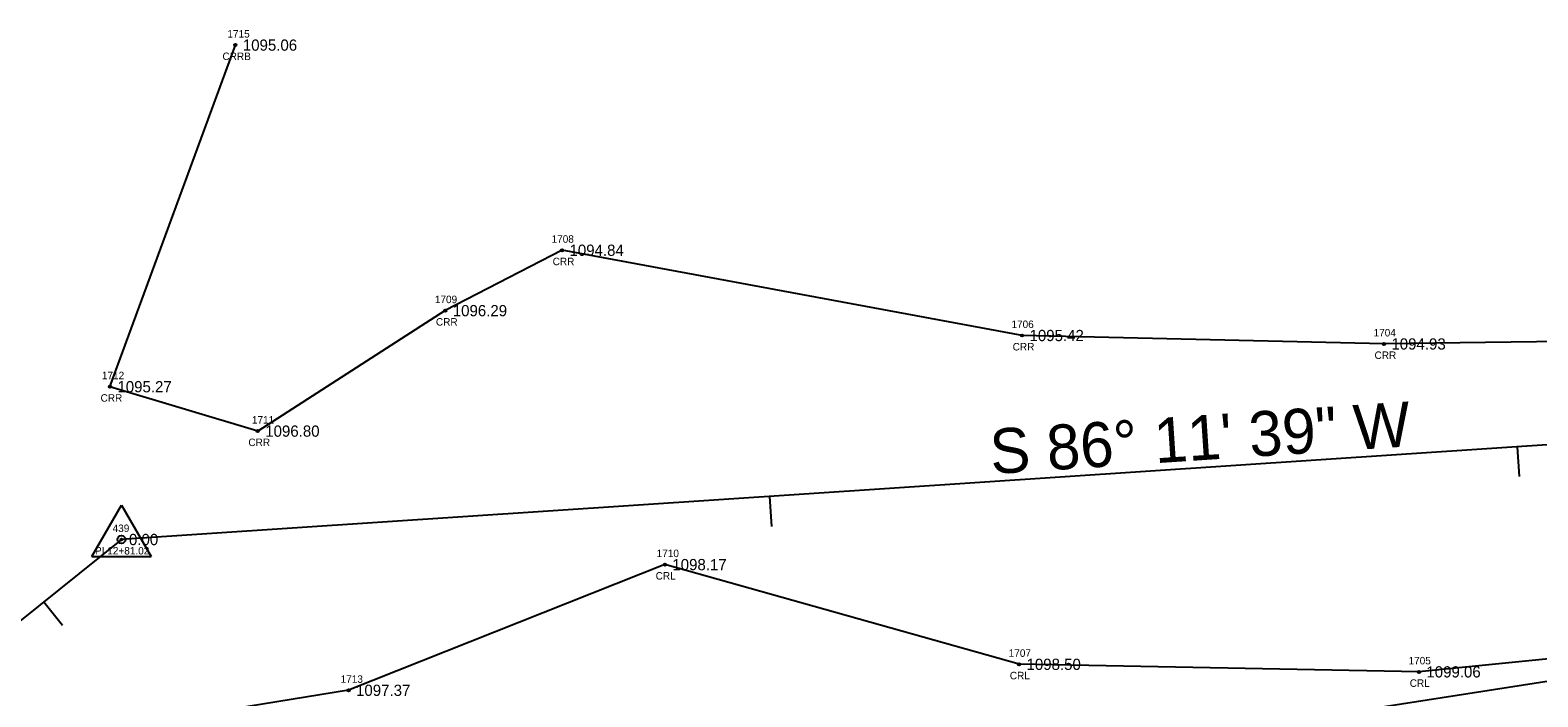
# Model space of a CAD drawing. Extents: x 1539151 to 1541799, y 1198646 to 1201165.
# Drawn here: x 1540955 to 1541156.3, y 1200424.1 to 1200513.1 of the extents above; entities that cross this region are included whole.
import ezdxf

# ---------------------------------------------------------------- set-up
doc = ezdxf.new("R2010")
doc.units = 0
for name, color, linetype in [('RD_EX_H2O', 7, 'Continuous'), ('RD_EX_H2O_txCode', 7, 'Continuous'), ('RD_EX_TX_H2O_ELEV', 7, 'Continuous'), ('RD_EX_VEG', 7, 'Continuous'), ('RD_HC_Cl', 7, 'Continuous'), ('RD_HC_Data', 7, 'Continuous'), ('RD_HC_Data_Tic', 7, 'Continuous'), ('RD_HC_Survey_ELEV', 7, 'Continuous'), ('RD_HC_txCode', 7, 'Continuous'), ('RD_SMD_Locator', 7, 'Continuous')]:
    doc.layers.add(name, color=color, linetype=linetype)

msp = doc.modelspace()

# ---------------------------------------------------------------- linework, layer by layer
at = {"layer": 'RD_EX_H2O'}
for points in [[(1541242.5, 1200488.61), (1541190.01, 1200471.92), (1541135.71, 1200471.19), (1541087.41, 1200472.32), (1541026.01, 1200483.71), (1541010.43, 1200475.64), (1540985.4, 1200459.55), (1540965.67, 1200465.48), (1540982.41, 1200511.11)], [(1541252.92, 1200441.86), (1541200.84, 1200433.45), (1541140.38, 1200427.39), (1541087.01, 1200428.4), (1541039.74, 1200441.72), (1540997.52, 1200424.93), (1540957.07, 1200418.34), (1540937.15, 1200404.81), (1540902.14, 1200374.36), (1540871.55, 1200334.52), (1540843.47, 1200300.89), (1540819.98, 1200290.97), (1540796.2, 1200252.53), (1540767.65, 1200218.32), (1540745.65, 1200154.73), (1540745.24, 1200145.69), (1540714.12, 1200111.24)]]:
    msp.add_lwpolyline(points, dxfattribs=at)
at = {"layer": 'RD_EX_VEG'}
msp.add_lwpolyline([(1541184.89, 1200430.38), (1541110.91, 1200418.83), (1540957.41, 1200347.72), (1540870.98, 1200282.61), (1540802.21, 1200226.22), (1540781.04, 1200235.77)], dxfattribs=at)
at = {"layer": 'RD_HC_Cl'}
for p, q in [((1541253.28, 1200464.1), (1540967.21, 1200445.07)), ((1540967.21, 1200445.07), (1540815.59, 1200323.52))]:
    msp.add_line(p, q, dxfattribs=at)
at = {"layer": 'RD_HC_Data'}
for p, q in [((1540963.24, 1200442.78), (1540967.22, 1200449.66)), ((1540967.22, 1200449.66), (1540971.18, 1200442.78)), ((1540963.24, 1200442.78), (1540971.18, 1200442.78))]:
    msp.add_line(p, q, dxfattribs=at)
msp.add_circle((1540967.21, 1200445.07), 0.529, dxfattribs=at)
at = {"layer": 'RD_HC_Data_Tic'}
for p, q in [((1541153.5, 1200457.46), (1541153.76, 1200453.47)), ((1541053.72, 1200450.82), (1541053.98, 1200446.83)), ((1540956.83, 1200436.75), (1540959.33, 1200433.63))]:
    msp.add_line(p, q, dxfattribs=at)
at = {"layer": 'RD_SMD_Locator'}
for centre in [(1540982.41, 1200511.11), (1541026.01, 1200483.71), (1541010.43, 1200475.64), (1541087.41, 1200472.32), (1541135.71, 1200471.19), (1540965.67, 1200465.48), (1540985.4, 1200459.55), (1540967.21, 1200445.07), (1541039.74, 1200441.72), (1541087.01, 1200428.4), (1541140.38, 1200427.39), (1540997.52, 1200424.93)]:
    msp.add_circle(centre, 0.15, dxfattribs=at)

# ---------------------------------------------------------------- texts
at = {"layer": 'RD_EX_H2O_txCode'}
for s, p in [('1715', (1540981.35, 1200512.11)), ('CRRB', (1540980.69, 1200509.11)), ('1708', (1541024.62, 1200484.71)), ('CRR', (1541024.76, 1200481.71)), ('1709', (1541009.04, 1200476.64)), ('CRR', (1541009.18, 1200473.64)), ('1706', (1541086, 1200473.32)), ('1704', (1541134.33, 1200472.19)), ('CRR', (1541086.16, 1200470.32)), ('CRR', (1541134.46, 1200469.19)), ('1712', (1540964.6, 1200466.48)), ('CRR', (1540964.42, 1200463.48)), ('1711', (1540984.62, 1200460.55)), ('CRR', (1540984.15, 1200457.55)), ('1710', (1541038.64, 1200442.72)), ('CRL', (1541038.51, 1200439.72)), ('1707', (1541085.63, 1200429.4)), ('1705', (1541139, 1200428.39)), ('1713', (1540996.46, 1200425.93)), ('CRL', (1541085.78, 1200426.4)), ('CRL', (1541139.16, 1200425.39))]:
    msp.add_text(s, height=1, dxfattribs=at).set_placement(p)
at = {"layer": 'RD_EX_TX_H2O_ELEV'}
for s, p in [('1095.06', (1540983.41, 1200510.36)), ('1094.84', (1541027.01, 1200482.96)), ('1096.29', (1541011.43, 1200474.89)), ('1095.42', (1541088.41, 1200471.57)), ('1094.93', (1541136.71, 1200470.44)), ('1095.27', (1540966.67, 1200464.73)), ('1096.80', (1540986.4, 1200458.8)), ('1098.17', (1541040.74, 1200440.97)), ('1098.50', (1541088.01, 1200427.65)), ('1099.06', (1541141.38, 1200426.64)), ('1097.37', (1540998.52, 1200424.18))]:
    msp.add_text(s, height=1.5, dxfattribs=at).set_placement(p)
at = {"layer": 'RD_HC_Data'}
msp.add_text('S 86%%d 11\' 39" W', height=6, rotation=3.8059, dxfattribs=at).set_placement((1541083.33, 1200453.8))
at = {"layer": 'RD_HC_Survey_ELEV'}
msp.add_text('0.00', height=1.5, dxfattribs=at).set_placement((1540968.21, 1200444.32))
at = {"layer": 'RD_HC_txCode'}
for s, p in [('439', (1540966.03, 1200446.07)), ('PI 12+81.02', (1540963.68, 1200443.07))]:
    msp.add_text(s, height=1, dxfattribs=at).set_placement(p)

doc.saveas('drawing.dxf')
